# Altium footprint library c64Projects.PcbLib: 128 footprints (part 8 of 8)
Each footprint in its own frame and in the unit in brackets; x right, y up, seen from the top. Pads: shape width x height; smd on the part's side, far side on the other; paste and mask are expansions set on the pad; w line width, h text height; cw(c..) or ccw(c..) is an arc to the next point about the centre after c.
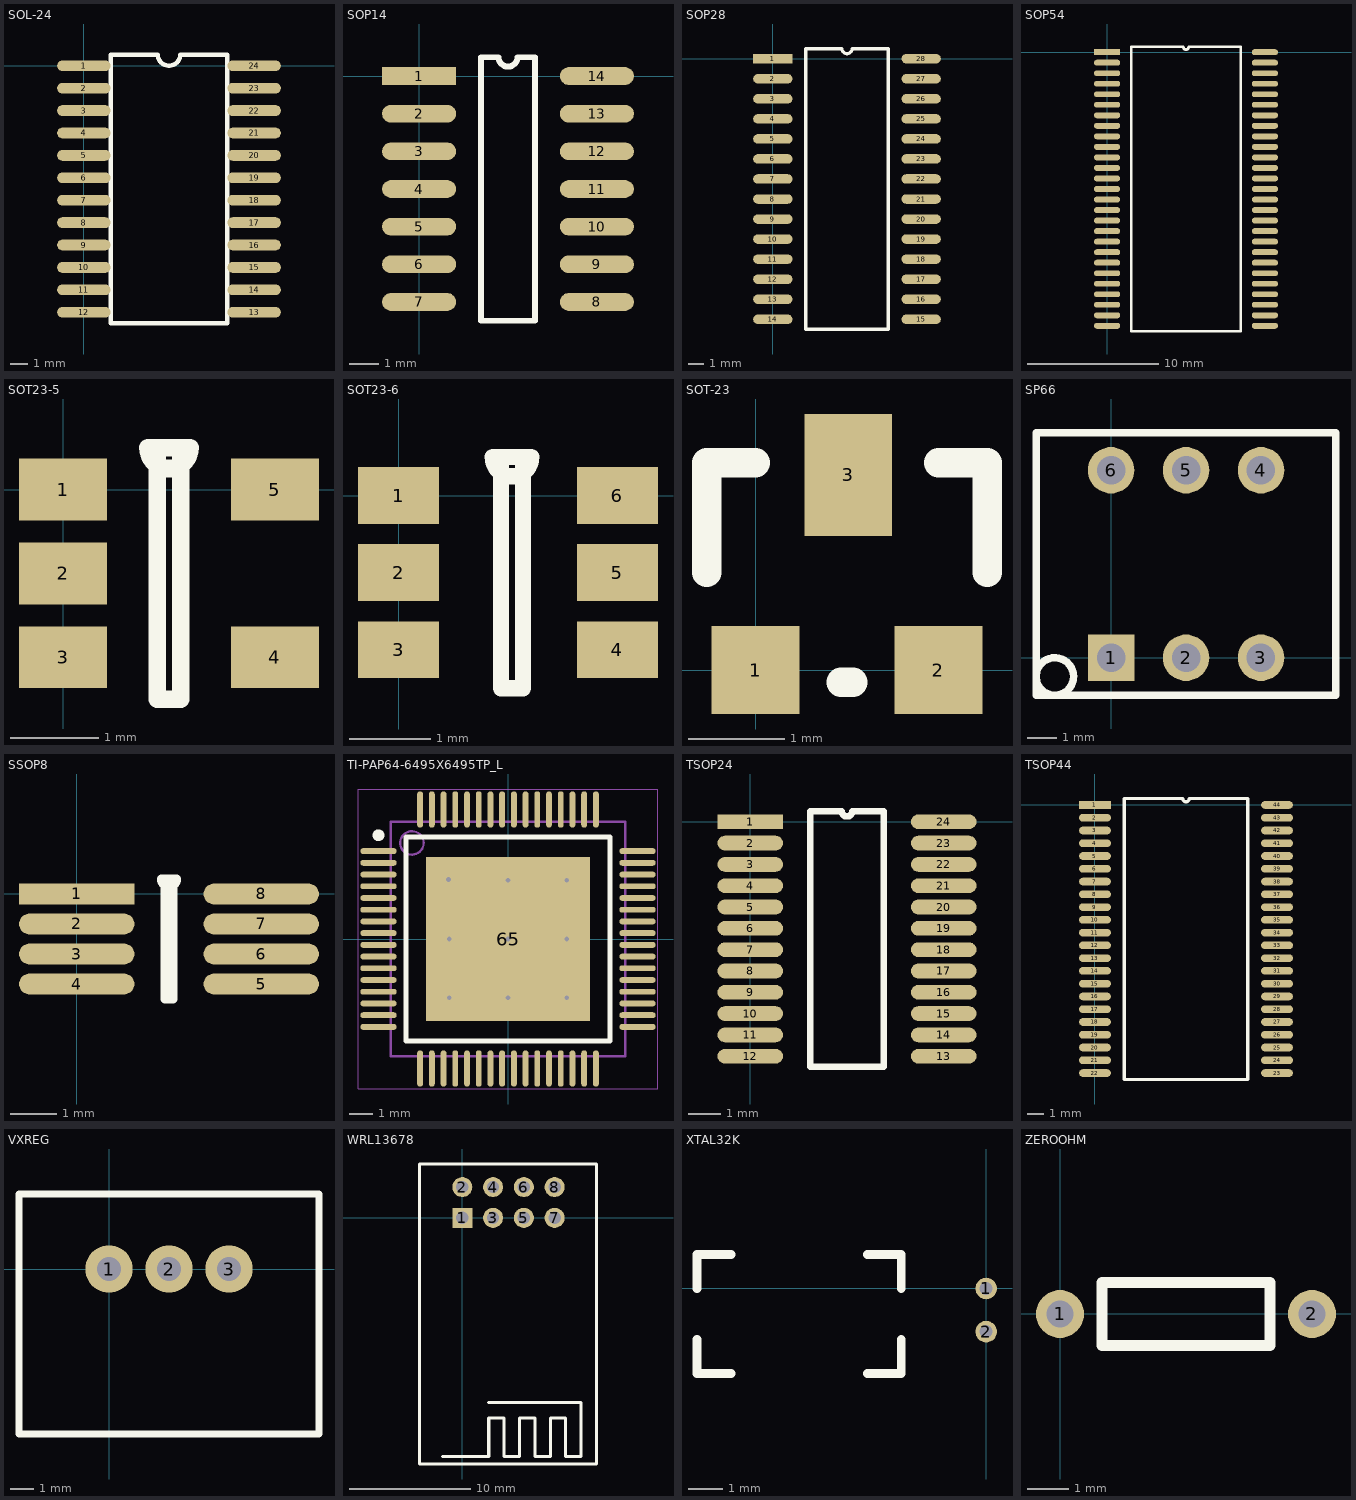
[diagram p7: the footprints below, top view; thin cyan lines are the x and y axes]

## SOL-24 [mil]
pads (24):
  oval 119.37x24 smd: 1(0,0) 2(0,-50) 3(0,-100) 4(0,-150) 5(0,-200) 6(0,-250) 7(0,-300) 8(0,-350) 9(0,-400) 10(0,-450) 11(0,-500) 12(0,-550) 13(380,-550) 14(380,-500) 15(380,-450) 16(380,-400) 17(380,-350) 18(380,-300) 19(380,-250) 20(380,-200) 21(380,-150) 22(380,-100) 23(380,-50) 24(380,0)
Top Overlay:
  lines w10: 60,-575 60,25 165,25 ccw(c190,25) 215,25 320,25 320,-575 60,-575

## SOP14 [mm]
pads (14):
  rect 2.5x0.6 smd: 1(0,0)
  oval 2.5x0.6 smd: 2(0,-1.27) 3(0,-2.54) 4(0,-3.81) 5(0,-5.08) 6(0,-6.35) 7(0,-7.62) 8(6,-7.62) 9(6,-6.35) 10(6,-5.08) 11(6,-3.81) 12(6,-2.54) 13(6,-1.27) 14(6,0)
Top Overlay:
  lines w0.2: 2.085,-8.255 2.085,0.635 2.682,0.635 ccw(c3,0.635) 3.317,0.635 3.915,0.635 3.915,-8.255 2.085,-8.255

## SOP28 [mm]
pads (28):
  rect 2.5x0.6 smd: 1(0,0)
  oval 2.5x0.6 smd: 2(0,-1.27) 3(0,-2.54) 4(0,-3.81) 5(0,-5.08) 6(0,-6.35) 7(0,-7.62) 8(0,-8.89) 9(0,-10.16) 10(0,-11.43) 11(0,-12.7) 12(0,-13.97) 13(0,-15.24) 14(0,-16.51) 15(9.4,-16.51) 16(9.4,-15.24) 17(9.4,-13.97) 18(9.4,-12.7) 19(9.4,-11.43) 20(9.4,-10.16) 21(9.4,-8.89) 22(9.4,-7.62) 23(9.4,-6.35) 24(9.4,-5.08) 25(9.4,-3.81) 26(9.4,-2.54) 27(9.4,-1.27) 28(9.4,0)
Top Overlay:
  lines w0.2: 2.085,-17.145 7.315,-17.145 7.315,0.635 5.017,0.635 cw(c4.7,0.635) 4.382,0.635 2.085,0.635 2.085,-17.145

## SOP54 [mm]
pads (54):
  rect 2x0.45 smd: 1(0,0)
  oval 2x0.45 smd: 2(0,-0.8) 3(0,-1.6) 4(0,-2.4) 5(0,-3.2) 6(0,-4) 7(0,-4.8) 8(0,-5.6) 9(0,-6.4) 10(0,-7.2) 11(0,-8) 12(0,-8.8) 13(0,-9.6) 14(0,-10.4) 15(0,-11.2) 16(0,-12) 17(0,-12.8) 18(0,-13.6) 19(0,-14.4) 20(0,-15.2) 21(0,-16) 22(0,-16.8) 23(0,-17.6) 24(0,-18.4) 25(0,-19.2) 26(0,-20) 27(0,-20.8) 28(12,-20.8) 29(12,-20) 30(12,-19.2) 31(12,-18.4) 32(12,-17.6) 33(12,-16.8) 34(12,-16) 35(12,-15.2) 36(12,-14.4) 37(12,-13.6) 38(12,-12.8) 39(12,-12) 40(12,-11.2) 41(12,-10.4) 42(12,-9.6) 43(12,-8.8) 44(12,-8) 45(12,-7.2) 46(12,-6.4) 47(12,-5.6) 48(12,-4.8) 49(12,-4) 50(12,-3.2) 51(12,-2.4) 52(12,-1.6) 53(12,-0.8) 54(12,0)
Top Overlay:
  lines w0.2: 1.835,-21.2 10.165,-21.2 10.165,0.4 6.2,0.4 cw(c6,0.4) 5.8,0.4 1.835,0.4 1.835,-21.2

## SOT23-5 [mm]
pads (5):
  rect 1x0.7 smd: 1(0,0) 2(0,-0.95) 3(0,-1.9) 4(2.4,-1.9) 5(2.4,0)
Top Overlay:
  lines w0.2: 0.962,0.475 ccw(c1.2,0.475) 1.438,0.475 1.065,0.475 1.065,-2.375 1.335,-2.375 1.335,0.475 0.962,0.475

## SOT23-6 [mm]
pads (6):
  rect 1x0.7 smd: 1(0,0) 2(0,-0.95) 3(0,-1.9) 4(2.7,-1.9) 5(2.7,-0.95) 6(2.7,0)
Top Overlay:
  lines w0.2: 1.162,0.475 ccw(c1.4,0.475) 1.637,0.475 1.265,0.475 1.265,-2.375 1.535,-2.375 1.535,0.475 1.162,0.475

## SOT-23 [mil]
pads (3):
  rect 36x36 smd: 1(0,0) 2(75,0)
  rect 36x50 smd: 3(38,80)
Top Overlay:
  lines w12: -20,40 -20,85 0,85 ; 35,-5 40,-5 ; 75,85 95,85 95,40

## SP66 [mil]
pads (6):
  rect 62x62 hole 38: 1(0,0)
  round 62 hole 38: 2(100,0) 3(200,0) 4(200,250) 5(100,250) 6(0,250)
Top Overlay:
  circle w10: c-75,-25 r25
  lines w10: -100,-50 300,-50 300,300 -100,300 -100,-50

## SSOP8 [mm]
pads (8):
  rect 2.5x0.451 smd: 1(0,0)
  oval 2.5x0.451 smd: 2(0,-0.65) 3(0,-1.3) 4(0,-1.95) 5(4,-1.95) 6(4,-1.3) 7(4,-0.65) 8(4,0)
Top Overlay:
  lines w0.2: 1.837,0.325 ccw(c2,0.325) 2.162,0.325 1.915,0.325 1.915,-2.275 2.085,-2.275 2.085,0.325 1.837,0.325

## TI-PAP64-6495X6495TP_L [mm] "QFP, 64-Leads, Body 10x10mm, Pitch 0.5mm, Thermal Pad 7x7mm, IPC High Density"
height 1.2
pads (65):
  oval 1.55x0.25 smd: 1(-5.525,3.75) 2(-5.525,3.25) 3(-5.525,2.75) 4(-5.525,2.25) 5(-5.525,1.75) 6(-5.525,1.25) 7(-5.525,0.75) 8(-5.525,0.25) 9(-5.525,-0.25) 10(-5.525,-0.75) 11(-5.525,-1.25) 12(-5.525,-1.75) 13(-5.525,-2.25) 14(-5.525,-2.75) 15(-5.525,-3.25) 16(-5.525,-3.75) 33(5.525,-3.75) 34(5.525,-3.25) 35(5.525,-2.75) 36(5.525,-2.25) 37(5.525,-1.75) 38(5.525,-1.25) 39(5.525,-0.75) 40(5.525,-0.25) 41(5.525,0.25) 42(5.525,0.75) 43(5.525,1.25) 44(5.525,1.75) 45(5.525,2.25) 46(5.525,2.75) 47(5.525,3.25) 48(5.525,3.75)
  oval 0.25x1.55 smd: 17(-3.75,-5.525) 18(-3.25,-5.525) 19(-2.75,-5.525) 20(-2.25,-5.525) 21(-1.75,-5.525) 22(-1.25,-5.525) 23(-0.75,-5.525) 24(-0.25,-5.525) 25(0.25,-5.525) 26(0.75,-5.525) 27(1.25,-5.525) 28(1.75,-5.525) 29(2.25,-5.525) 30(2.75,-5.525) 31(3.25,-5.525) 32(3.75,-5.525) 49(3.75,5.525) 50(3.25,5.525) 51(2.75,5.525) 52(2.25,5.525) 53(1.75,5.525) 54(1.25,5.525) 55(0.75,5.525) 56(0.25,5.525) 57(-0.25,5.525) 58(-0.75,5.525) 59(-1.25,5.525) 60(-1.75,5.525) 61(-2.25,5.525) 62(-2.75,5.525) 63(-3.25,5.525) 64(-3.75,5.525)
  rect 7x7 smd: 65(0,0)
via -2.54,2.54 diameter 0.5 hole 0.2
via 0,2.5 diameter 0.5 hole 0.2
via 2.5,2.5 diameter 0.5 hole 0.2
via -2.5,-2.5 diameter 0.5 hole 0.2
via 0,-2.5 diameter 0.5 hole 0.2
via 2.5,-2.5 diameter 0.5 hole 0.2
via -2.5,0 diameter 0.5 hole 0.2
via 0,0 diameter 0.5 hole 0.2
via 2.5,0 diameter 0.5 hole 0.2
Top Overlay:
  circle w0.25: c-5.525,4.425 r0.125
  lines w0.2: -4.35,-4.35 4.35,-4.35 4.35,4.35 -4.35,4.35 -4.35,-4.35
3D Top:
  circle w0.1: c-4.1,4.1 r0.5
  lines w0.1: -5,-5 5,-5 5,5 -5,5 -5,-5
Courtyard Top:
  lines w0.05: -6.4,-6.4 6.4,-6.4 6.4,6.4 -6.4,6.4 -6.4,-6.4
  lines w0.1: -0.5,0 0.5,0 ; 0,-0.5 0,0.5
3D body: height 1.2, standoff 0.05, extent -5,-5 5,5

## TSOP24 [mm]
pads (24):
  rect 2x0.45 smd: 1(0,0)
  oval 2x0.45 smd: 2(0,-0.65) 3(0,-1.3) 4(0,-1.95) 5(0,-2.6) 6(0,-3.25) 7(0,-3.9) 8(0,-4.55) 9(0,-5.2) 10(0,-5.85) 11(0,-6.5) 12(0,-7.15) 13(5.9,-7.15) 14(5.9,-6.5) 15(5.9,-5.85) 16(5.9,-5.2) 17(5.9,-4.55) 18(5.9,-3.9) 19(5.9,-3.25) 20(5.9,-2.6) 21(5.9,-1.95) 22(5.9,-1.3) 23(5.9,-0.65) 24(5.9,0)
Top Overlay:
  lines w0.2: 1.835,-7.475 1.835,0.325 2.788,0.325 ccw(c2.95,0.325) 3.112,0.325 4.065,0.325 4.065,-7.475 1.835,-7.475

## TSOP44 [mm]
pads (44):
  rect 2x0.477 smd: 1(0,0)
  oval 2x0.477 smd: 2(0,-0.8) 3(0,-1.6) 4(0,-2.4) 5(0,-3.2) 6(0,-4) 7(0,-4.8) 8(0,-5.6) 9(0,-6.4) 10(0,-7.2) 11(0,-8) 12(0,-8.8) 13(0,-9.6) 14(0,-10.4) 15(0,-11.2) 16(0,-12) 17(0,-12.8) 18(0,-13.6) 19(0,-14.4) 20(0,-15.2) 21(0,-16) 22(0,-16.8) 23(11.41,-16.8) 24(11.41,-16) 25(11.41,-15.2) 26(11.41,-14.4) 27(11.41,-13.6) 28(11.41,-12.8) 29(11.41,-12) 30(11.41,-11.2) 31(11.41,-10.4) 32(11.41,-9.6) 33(11.41,-8.8) 34(11.41,-8) 35(11.41,-7.2) 36(11.41,-6.4) 37(11.41,-5.6) 38(11.41,-4.8) 39(11.41,-4) 40(11.41,-3.2) 41(11.41,-2.4) 42(11.41,-1.6) 43(11.41,-0.8) 44(11.41,0)
Top Overlay:
  lines w0.2: 1.835,-17.2 9.575,-17.2 9.575,0.4 5.905,0.4 cw(c5.705,0.4) 5.505,0.4 1.835,0.4 1.835,-17.2

## VXREG [mm]
pads (3):
  round 2 hole 1 mask+0.254: 1(0,0) 2(2.54,0) 3(5.08,0)
Top Overlay:
  lines w0.305: -3.81,-6.985 -3.81,3.175 8.89,3.175 8.89,-6.985 -3.81,-6.985

## WRL13678 [mil]
pads (8):
  rect 65x65 hole 40: 1(0,0)
  round 65 hole 40: 2(0,100) 3(100,0) 4(100,100) 5(200,0) 6(200,100) 7(300,0) 8(300,100)
Top Overlay:
  lines w10: -63.97,-775 86.03,-775 86.03,-650 136.03,-650 136.03,-775 186.03,-775 186.03,-650 236.03,-650 236.03,-775 286.03,-775 286.03,-650 336.03,-650 336.03,-775 386.03,-775 386.03,-600 86.03,-600 ; -138.97,-800 436.03,-800 436.03,175 -138.97,175 -138.97,-800

## XTAL32K [mil]
pads (2):
  round 25 hole 15 unplated mask+10: 1(0,0) 2(0,-50)
Top Overlay:
  lines w10: -334.65,-59.06 -334.65,-98.43 -295.28,-98.43 ; -334.65,0 -334.65,39.37 -295.28,39.37 ; -137.8,-98.43 -98.43,-98.43 -98.43,-59.06 ; -137.8,39.37 -98.43,39.37 -98.43,0

## ZEROOHM [mil]
pads (2):
  round 45 hole 25: 1(0,0) 2(236.22,0)
Top Overlay:
  lines w10: 39.37,-29.53 196.85,-29.53 196.85,29.53 39.37,29.53 39.37,-29.53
